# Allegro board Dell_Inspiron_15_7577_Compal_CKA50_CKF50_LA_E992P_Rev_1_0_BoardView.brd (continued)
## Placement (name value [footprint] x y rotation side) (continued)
CH113  10U_0603_6.3V6M  [C_0603]  176.82 115.73 90 top
CH114  10U_0603_6.3V6M  [C_0603]  173.89 91.03 180 top
CH115  10U_0603_6.3V6M  [C_0603]  178.03 115.73 90 top
CH116  10U_0603_6.3V6M  [C_0603]  179.24 115.73 90 top
CH117  10U_0603_6.3V6M  [C_0603]  173.78 95.47 180 top
CH118  10U_0603_6.3V6M  [C_0603]  153.35 85.07 90 top
CH119  10U_0603_6.3V6M  [C_0603]  158.13 84.88 90 top
CH120  10U_0603_6.3V6M  [C_0603]  155.04 81.5 270 top
CH121  10U_0603_6.3V6M  [C_0603]  152.38 83.98 270 top
CH122  10U_0603_6.3V6M  [C_0603]  159.82 84.44 90 top
CH123  10U_0603_6.3V6M  [C_0603]  165.2 81.05 270 top
CH124  10U_0402_6.3V6M  [C_0402]  151.7 85.07 90 top
CH125  10U_0603_6.3V6M  [C_0603]  163.46 83.78 90 top
CH126  10U_0603_6.3V6M  [C_0603]  168.12 80.48 270 top
CH127  10U_0603_6.3V6M  [C_0603]  173.84 85.85 180 top
CH128  10U_0603_6.3V6M  [C_0603]  172.9 80.17 90 top
CH129  22U_0603_6.3V6M  [C_0603]  179.22 65.4 0 top
CH130  22U_0603_6.3V6M  [C_0603]  179.22 64 0 top
CH131  22U_0603_6.3V6M  [C_0603]  179.22 62.61 0 top
CH132  22U_0603_6.3V6M  [C_0603]  179.22 61.21 0 top
CH133  1U_0402_6.3V6K  [C_0402]  172.57 103.28 90 top
CH134  1U_0402_6.3V6K  [C_0402]  180.38 115.92 90 top
CH135  1U_0402_6.3V6K  [C_0402]  172.57 101.5 90 top
CH136  47U_0603_6.3V6M  [C_0603]  173.98 92.25 180 top
CH173  0.1U_0402_10V6K  [C_0402]  285.43 33.43 90 top
CH176  1U_0402_6.3V6K  [C_0402]  281.85 32.53 90 top
CH177  22U_0603_6.3V6M  [C_0603]  301.64 46.83 90 bottom
CH178  22U_0603_6.3V6M  [C_0603]  300.37 46.83 90 bottom
CH179  1U_0402_6.3V6K  [C_0402]  299.31 46.88 90 bottom
CH180  1U_0402_6.3V6K  [C_0402]  273.69 50.97 270 top
CH181  22U_0603_6.3V6M  [C_0603]  275.8 53.5 180 top
CH182  22U_0603_6.3V6M  [C_0603]  276.1 51.21 270 top
CH183  1U_0402_6.3V6K  [C_0402]  283.45 44.29 180 top
CH184  10U_0402_6.3V6M  [C_0402]  283.99 45.17 90 top
CH185  10U_0402_6.3V6M  [C_0402]  283.1 45.17 90 top
CH186  0.1U_0402_10V6K  [C_0402]  288.84 31.99 90 top
CH187  1U_0402_6.3V6K  [C_0402]  288.77 30.84 270 top
CH188  1U_0402_6.3V6K  [C_0402]  290.84 40.12 0 top
CH189  0.1U_0402_10V7K  [C_0402]  293.93 34.95 180 top
CH190  0.1U_0402_10V7K  [C_0402]  277.95 41.85 180 top
CH191  0.1U_0402_10V7K  [C_0402]  280.65 40.92 180 top
CH192  0.1U_0402_10V7K  [C_0402]  273.8 30.51 180 top
CH197  0.1U_0402_10V7K  [C_0402]  133.51 87.55 180 bottom
CH200  0.1U_0402_10V6K  [C_0402]  289.96 32.9 90 top
CH201  22U_0603_6.3V6M  [C_0603]  295.44 36.41 90 top
CH202  22U_0603_6.3V6M  [C_0603]  296.65 36.41 90 top
CH203  0.1U_0402_10V6K  [C_0402]  288.91 35.88 0 top
CH204  1U_0402_6.3V6K  [C_0402]  175.29 99.09 180 top
CH205  0.1U_0402_10V7K  [C_0402]  189.9 64.72 90 top
CH206  0.1U_0402_10V7K  [C_0402]  200.19 57.95 270 top
CH207  0.1U_0402_10V7K  [C_0402]  201.32 65.56 0 top
CH208  100P_0402_50V8J  [C_0402]  284.14 31.16 270 top
CH209  100P_0402_50V8J  [C_0402]  300.04 30 90 bottom
CH210  100P_0402_50V8J  [C_0402]  179.85 80.93 90 top
CH211  100P_0402_50V8J  [C_0402]  137.42 99.98 180 bottom
CH212  100P_0402_50V8J  [C_0402]  295.75 34.51 0 top
CH213  0.5P_0402_50V8C  [C_0402]  290.95 31.66 270 top
CH214  0.5P_0402_50V8C  [C_0402]  283.2 42.45 180 top
CH215  10P_0402_25V8J  [C_0402]  283.61 22.77 270 bottom
CI3  0.1U_0402_10V7K  [C_0402]  11.6 53.42 90 bottom
CI4  0.01U_0402_16V7K  [C_0402]  6.71 45.44 270 bottom
CI5  0.1U_0402_10V7K  [C_0402]  9.69 44.53 90 bottom
CI6  0.1U_0402_10V7K  [C_0402]  10.64 44.53 90 bottom
CI7  0.1U_0402_10V7K  [C_0402]  7.72 44.53 90 bottom
CI8  0.1U_0402_10V7K  [C_0402]  8.68 44.53 90 bottom
CI9  0.1U_0402_10V6K  [C_0402]  356.45 29.05 0 top
CI10  0.1U_0402_10V6K  [C_0402]  356.45 28.16 0 top
CI11  47U_0805_6.3V6M  [C_0805]  360.19 24.73 180 top
CI12  10U_0603_6.3V6M  [C_0603]  363.73 23.15 180 bottom
CI13  0.1U_0402_10V6K  [C_0402]  363.25 24.31 180 bottom
CI16  0.1U_0402_10V6K  [C_0402]  362.18 35 90 top
CI17  47U_0805_6.3V6M  [C_0805]  363.83 35.91 180 bottom
CI18  10U_0603_6.3V6M  [C_0603]  363.83 37.37 180 bottom
CI19  0.1U_0402_10V6K  [C_0402]  363.88 38.45 180 bottom
CI20  0.1U_0402_10V6K  [C_0402]  363.07 35 90 top
CI21  100U_1206_6.3V6K  [C_1206]  18.2 63.72 0 top
CI23  0.1U_0402_10V6K  [C_0402]  12.85 37.68 0 bottom
CI24  1U_0402_6.3V6K  [C_0402]  350.14 33.72 90 bottom
CI25  0.1U_0402_10V6K  [C_0402]  18.5 68.29 0 top
CI26  10U_0603_6.3V6M  [C_0603]  18.45 67.21 0 top
CI27  47U_0805_6.3V6M  [C_0805]  18.37 65.69 0 top
CI28  0.1U_0402_10V7K  [C_0402]  21.74 58.56 90 top
CI29  0.1U_0402_10V7K  [C_0402]  20.79 58.56 90 top
CI30  100U_1206_6.3V6K  [C_1206]  364.97 37.81 0 bottom
CI31  47U_0805_6.3V6M  [C_0805]  360.19 22.95 180 top
CL15  0.1U_0402_10V6K  [C_0402]  30.85 45.58 270 top
CL19  0.1U_0402_10V6K  [C_0402]  22.99 49.33 180 bottom
CL20  0.1U_0402_10V6K  [C_0402]  25.77 49.43 180 bottom
CL21  0.1U_0402_10V6K  [C_0402]  24 41.47 270 top
CL22  0.1U_0402_10V6K  [C_0402]  27.71 49.43 0 bottom
CL24  0.1U_0402_10V6K  [C_0402]  22.78 47.4 180 bottom
CL30  0.1U_0402_10V6K  [C_0402]  29.96 41.56 180 bottom
CL31  0.1U_0402_10V6K  [C_0402]  29.96 40.6 180 bottom
CL32  0.1U_0402_10V6K  [C_0402]  25.6 41.57 270 bottom
CL33  10P_1206_2KV8J  [C_1206]  21.25 79.47 90 top
CL34  0.1U_0402_10V6K  [C_0402]  25.77 50.38 180 bottom
CL35  1U_0402_6.3V6K  [C_0402]  24.65 41.57 270 bottom
CL36  10P_0402_25V8J  [C_0402]  21.88 45.58 90 bottom
CL37  10P_0402_25V8J  [C_0402]  21.88 44.71 270 bottom
CL39  1U_0402_6.3V6K  [C_0402]  24.09 55.72 0 bottom
CL41  1000P_0402_50V7K  [C_0402]  22.01 65.26 270 top
CL42  0.1U_0402_10V7K  [C_0402]  23.7 41.57 270 bottom
CL43  4.7U_0402_6.3V6M  [C_0402]  29.93 45.58 270 top
CL44  4.7U_0402_6.3V6M  [C_0402]  24.09 47.15 0 top
CL47  0.1U_0402_10V6K  [C_0402]  30.85 45.34 180 bottom
CL48  0.1U_0402_10V6K  [C_0402]  30.85 44.45 180 bottom
CL49  0.1U_0402_25V6  [C_0402]  29.95 65.26 270 top
CL52  1000P_0402_50V7K  [C_0402]  23.91 65.27 270 top
CL53  0.1U_0402_25V6  [C_0402]  24.93 65.26 270 top
CL54  1000P_0402_50V7K  [C_0402]  30.9 65.26 270 top
CL55  0.1U_0402_25V6  [C_0402]  22.96 65.26 270 top
CL56  1000P_0402_50V7K  [C_0402]  26.96 65.26 270 top
CL57  0.1U_0402_25V6  [C_0402]  27.91 65.25 270 top
CLP1  -  [EMIST_SUL-12A2M_1P]  367.77 78.77 180 bottom
CLP2  -  [EMIST_SUL-12A2M_1P]  365.74 39.72 180 bottom
CLP3  -  [EMIST_SUL-12A2M_1P]  343.64 60.23 270 bottom
CLP4  -  [EMIST_SUL-12A2M_1P]  348.13 69.43 229 bottom
CLRP1  SHORT PADS  [SHORTPADS]  294.59 22.77 180 bottom
CN1  22U_0603_6.3V6M  [C_0603]  338.94 34.64 90 top
CN2  .1U_0402_16V7K  [C_0402]  340.08 34.62 90 top
CN6  22U_0603_6.3V6M  [C_0603]  342.49 33.49 270 top
CN7  .1U_0402_16V7K  [C_0402]  341.29 33.51 270 top
CN9  10P_0402_25V8J  [C_0402]  341.22 34.94 90 top
CN19  0.1U_0402_16V7K  [C_0402]  264.97 11.13 180 top
CN20  0.1U_0402_10V7K  [C_0402]  344.67 42.51 0 top
CN21  0.1U_0402_10V7K  [C_0402]  344.67 41.56 0 top
CN22  10U_0603_6.3V6M  [C_0603]  270.1 11.65 90 top
CP3  0.01U_0402_16V7K  [C_0402]  328.16 46.57 180 top
CP4  0.1U_0402_10V6K  [C_0402]  328.16 47.53 180 top
CP5  0.1U_0402_10V6K  [C_0402]  341.53 51.91 0 top
CP6  0.1U_0402_10V6K  [C_0402]  341.53 51.02 0 top
CP7  0.01U_0402_16V7K  [C_0402]  341.53 52.8 0 top
CP8  4.7U_0603_6.3V6K  [C_0603]  337.03 40.1 0 top
CP9  0.1U_0402_10V6K  [C_0402]  334.44 40.29 180 top
CP10  0.01U_0402_16V7K  [C_0402]  334.44 39.4 180 top
CP11  0.1U_0402_10V6K  [C_0402]  336.02 40.24 270 top
CP12  0.1U_0402_10V6K  [C_0402]  334.11 49.99 90 top
CP13  0.1U_0402_10V6K  [C_0402]  336.49 49.99 0 top
CP14  0.01U_0402_16V7K  [C_0402]  336.49 50.88 0 top
CP15  0.1U_0402_10V6K  [C_0402]  340.53 39.32 90 top
CP16  0.1U_0402_10V6K  [C_0402]  339.64 39.32 90 top
CP17  0.1U_0402_10V6K  [C_0402]  330.05 39.45 90 top
CP18  0.1U_0402_10V6K  [C_0402]  330.94 39.45 90 top
CP19  0.1U_0402_10V6K  [C_0402]  332.51 37.16 90 top
CP20  0.1U_0402_10V6K  [C_0402]  333.4 37.16 90 top
CP21  0.1U_0402_10V6K  [C_0402]  335.7 37.16 90 top
CP22  0.1U_0402_10V6K  [C_0402]  334.81 37.16 90 top
CP23  0.1U_0402_10V6K  [C_0402]  338.42 49.9 270 top
CP24  0.1U_0402_10V6K  [C_0402]  329.91 51.78 0 top
CP25  0.01U_0402_16V7K  [C_0402]  339.26 41.87 0 top
CP26  0.1U_0402_10V6K  [C_0402]  329.91 50.89 0 top
CP27  1U_0402_6.3V6K  [C_0402]  328.41 42.95 180 top
CP28  22U_0603_6.3V6M  [C_0603]  337.05 38.59 0 top
CP29  22U_0603_6.3V6M  [C_0603]  327.53 48.45 90 top
CP47  0.1U_0402_16V7K  [C_0402]  331.7 49.91 180 top
CR4  6.8P_0402_50V8C  [C_0402]  13.5 23.32 90 bottom
CR5  4.7U_0603_6.3V6K  [C_0603]  20.37 40.3 0 top
CR6  0.1U_0402_10V7K  [C_0402]  20.92 39.21 0 top
CR7  1U_0402_6.3V6K  [C_0402]  15.53 23.32 90 bottom
CR8  1U_0402_6.3V6K  [C_0402]  11.14 29.75 0 bottom
CR9  0.1U_0402_10V7K  [C_0402]  17.31 32.16 180 bottom
CR10  4.7U_0603_6.3V6K  [C_0603]  17.86 33.25 180 bottom
CS12  1000P_0402_50V7K  [C_0402]  243.55 30.4 90 bottom
CS13  0.1U_0402_10V6K  [C_0402]  244.44 30.4 90 bottom
CS14  1U_0402_6.3V6K  [C_0402]  245.33 30.4 90 bottom
CS15  10U_0603_6.3V6M  [C_0603]  246.48 30.51 90 bottom
CS25  0.01U_0402_16V7K  [C_0402]  246.67 24.51 90 top
CS26  0.01U_0402_16V7K  [C_0402]  245.78 24.51 90 top
CS27  0.01U_0402_16V7K  [C_0402]  249.02 24.58 90 top
CS28  0.01U_0402_16V7K  [C_0402]  249.91 24.58 90 top
CT1  0.22U_0201_6.3V  [C_0201]  347.22 51.59 0 bottom
CT2  0.22U_0201_6.3V  [C_0201]  347.22 52.23 0 bottom
CT3  0.22U_0201_6.3V  [C_0201]  347.22 49.05 0 bottom
CT4  0.22U_0201_6.3V  [C_0201]  347.22 53.5 0 bottom
CT5  0.22U_0201_6.3V  [C_0201]  347.22 56.04 0 bottom
CT6  0.1U_0201_6.3V6K  [C_0201]  357.73 46.73 90 bottom
CT7  0.1U_0201_6.3V6K  [C_0201]  357.1 46.73 90 bottom
CT8  0.1U_0201_6.3V6K  [C_0201]  356.46 46.73 90 bottom
CT9  0.1U_0201_6.3V6K  [C_0201]  355.83 46.73 90 bottom
CT10  0.1U_0201_6.3V6K  [C_0201]  354.56 46.73 90 bottom
CT11  0.1U_0201_6.3V6K  [C_0201]  353.29 46.73 90 bottom
CT12  0.22U_0201_6.3V  [C_0201]  347.22 52.86 0 bottom
CT13  0.22U_0201_6.3V  [C_0201]  347.22 50.96 0 bottom
CT14  0.22U_0201_6.3V  [C_0201]  347.22 50.32 0 bottom
CT15  0.22U_0201_6.3V  [C_0201]  347.22 48.42 0 bottom
CT16  0.22U_0201_6.3V  [C_0201]  347.22 49.69 0 bottom
CT18  0.22U_0201_6.3V  [C_0201]  347.22 54.13 0 bottom
CT21  0.22U_0201_6.3V  [C_0201]  347.22 56.67 0 bottom
CT23  0.1U_0201_6.3V6K  [C_0201]  355.19 46.73 90 bottom
CT24  0.1U_0201_6.3V6K  [C_0201]  353.92 46.73 90 bottom
CT25  0.1U_0201_6.3V6K  [C_0201]  352.59 44.06 90 top
CT26  0.1U_0201_6.3V6K  [C_0201]  353.23 44.06 90 top
CT27  0.1U_0201_6.3V6K  [C_0201]  352.02 46.73 90 bottom
CT28  0.1U_0201_6.3V6K  [C_0201]  352.65 46.73 90 bottom
CT29  0.1U_0201_6.3V6K  [C_0201]  350.75 46.73 90 bottom
CT30  0.1U_0201_6.3V6K  [C_0201]  351.38 46.73 90 bottom
CT31  0.1U_0201_6.3V6K  [C_0201]  350.11 46.73 90 bottom
CT32  0.1U_0201_6.3V6K  [C_0201]  349.48 46.73 90 bottom
CT33  0.1U_0201_6.3V6K  [C_0201]  348.21 46.73 90 bottom
CT34  0.1U_0201_6.3V6K  [C_0201]  348.84 46.73 90 bottom
CT35  0.1U_0201_6.3V6K  [C_0201]  351.96 44.06 90 top
CT36  0.1U_0201_6.3V6K  [C_0201]  351.32 44.06 90 top
CT37  27P_0402_50V8J  [C_0402]  347.14 61.37 180 bottom
CT38  27P_0402_50V8J  [C_0402]  348.01 61.37 0 bottom
CT39  0.22U_0201_6.3V  [C_0201]  354.14 62.1 225 bottom
CT40  0.22U_0201_6.3V  [C_0201]  353.61 62.63 225 bottom
CT41  0.22U_0201_6.3V  [C_0201]  352.53 63.24 225 bottom
CT42  0.22U_0201_6.3V  [C_0201]  352.93 62.84 225 bottom
CT43  0.1U_0201_6.3V6K  [C_0201]  351.43 46.54 90 top
CT44  0.1U_0201_6.3V6K  [C_0201]  352 46.54 90 top
CT45  0.1U_0201_6.3V6K  [C_0201]  362.52 45.43 0 bottom
CT46  0.1U_0201_6.3V6K  [C_0201]  357.13 51.97 0 top
CT47  1U_0201_6.3V6M  [C_0201]  357.52 59.15 180 top
CT48  1U_0201_6.3V6M  [C_0201]  361.38 55.4 0 top
CT49  1U_0201_6.3V6M  [C_0201]  356.72 61.79 270 top
CT50  10U_0402_6.3V6M  [C_0402]  361.6 59.78 0 top
CT51  10U_0402_6.3V6M  [C_0402]  361.6 60.67 0 top
CT52  10U_0402_6.3V6M  [C_0402]  361.6 61.56 0 top
CT53  10U_0402_6.3V6M  [C_0402]  361.66 58.89 0 top
CT54  1U_0201_6.3V6M  [C_0201]  354.46 41.11 0 top
CT55  1U_0201_6.3V6M  [C_0201]  350.59 53.13 180 top
CT56  1U_0201_6.3V6M  [C_0201]  348.24 47.34 0 top
CT57  1U_0201_6.3V6M  [C_0201]  354.46 41.81 0 top
CT58  1U_0201_6.3V6M  [C_0201]  354.46 42.54 0 top
CT59  1U_0201_6.3V6M  [C_0201]  353.93 51.89 270 top
CT60  1U_0201_6.3V6M  [C_0201]  354.5 54.62 270 top
CT61  1U_0201_6.3V6M  [C_0201]  356.41 54.43 270 top
CT62  1U_0201_6.3V6M  [C_0201]  357.2 55.09 0 top
CT63  1U_0201_6.3V6M  [C_0201]  354.46 56.56 0 top
CT64  1U_0201_6.3V6M  [C_0201]  356.4 55.06 90 top
CT65  1U_0201_6.3V6M  [C_0201]  355.57 58.36 90 top
CT66  1U_0201_6.3V6M  [C_0201]  355 58.36 90 top
CT67  1U_0201_6.3V6M  [C_0201]  354.43 58.36 90 top
CT68  1U_0201_6.3V6M  [C_0201]  353.86 58.36 90 top
CT69  1U_0201_6.3V6M  [C_0201]  353.29 57.2 180 top
CT70  1U_0201_6.3V6M  [C_0201]  351.76 53.49 270 top
CT71  1U_0201_6.3V6M  [C_0201]  350.59 53.7 180 top
CT72  1U_0201_6.3V6M  [C_0201]  350.59 54.27 180 top
CT73  47U_0603_6.3V6M  [C_0603]  366.14 58.31 90 top
CT74  47U_0603_6.3V6M  [C_0603]  364.87 58.31 90 top
CT75  47U_0603_6.3V6M  [C_0603]  367.41 58.31 90 top
CT77  1U_0201_6.3V6M  [C_0201]  352.69 51.97 180 top
CT78  1U_0201_6.3V6M  [C_0201]  356.53 51.99 270 top
CT79  1U_0201_6.3V6M  [C_0201]  354.5 52.83 90 top
CT80  1U_0201_6.3V6M  [C_0201]  355.71 53.21 90 top
CT81  10U_0402_6.3V6M  [C_0402]  347.65 58.13 180 top
CT82  10U_0402_6.3V6M  [C_0402]  347.65 59.08 180 top
CT83  1U_0201_6.3V6M  [C_0201]  349.64 57.56 180 top
CT84  1U_0201_6.3V6M  [C_0201]  347.42 59.91 180 top
CT85  1U_0201_6.3V6M  [C_0201]  351.8 55.63 270 top
CT86  1U_0201_6.3V6M  [C_0201]  353.28 55.86 90 top
CT88  0.1U_0402_10V6K  [C_0402]  354.8 71.41 270 bottom
CT90  22U_0603_6.3V6M  [C_0603]  365.61 66.26 0 bottom
CT91  22U_0603_6.3V6M  [C_0603]  365.67 67.53 0 bottom
CT92  22U_0603_6.3V6M  [C_0603]  365.61 65.05 0 bottom
CT93  22U_0603_6.3V6M  [C_0603]  366.69 70.12 315 top
CT94  0.01U_0402_50V7K  [C_0402]  368.96 71.97 0 top
CT95  0.01U_0402_50V7K  [C_0402]  368.96 71.08 0 top
CT96  0.01U_0402_50V7K  [C_0402]  369.88 70.2 180 top
CT97  0.01U_0402_50V7K  [C_0402]  369.88 68.1 180 top
CT98  2.2U_0603_16V6K  [C_0603]  356.91 67.59 180 bottom
CT99  4.7U_0603_10V6K  [C_0603]  357.35 66 180 bottom
CT100  4.7U_0603_10V6K  [C_0603]  357.88 71.13 315 top
CT101  1U_0402_6.3V6K  [C_0402]  353.86 71.41 270 bottom
CT102  1U_0201_6.3V6M  [C_0201]  355.68 72.99 180 bottom
CT103  10U_0402_6.3V6M  [C_0402]  354.45 67.72 180 bottom
CT104  0.22U_0402_10V4Z  [C_0402]  364.4 76.28 90 bottom
CT106  1U_0603_25V6K  [C_0603]  372.21 73.31 90 bottom
CT108  0.22U_0201_6.3V  [C_0201]  347.22 55.4 0 bottom
CT109  0.22U_0201_6.3V  [C_0201]  347.22 54.77 0 bottom
CT110  0.22U_0201_6.3V  [C_0201]  347.22 57.31 0 bottom
CT111  0.22U_0201_6.3V  [C_0201]  347.22 57.94 0 bottom
CT112  220P_0201_25V7K  [C_0201]  364.47 74.67 90 bottom
CT113  220P_0201_25V7K  [C_0201]  365.91 73.73 0 bottom
CT114  2200P_0402_25V7K  [C_0402]  91.86 68.09 90 bottom
CT115  47U_0603_6.3V6M  [C_0603]  360.59 56.29 0 top
CT116  47U_0603_6.3V6M  [C_0603]  360.59 57.5 0 top
CT117  0.1U_0201_6.3V6K  [C_0201]  364.69 97.74 0 bottom
CTH1  0.1U_0201_10V6K  [C_0201]  93.55 65.5 180 bottom
CTH2  0.01U_0402_16V7K  [C_0402]  160.5 89.28 0 top
CTH3  2200P_0402_25V7K  [C_0402]  90.78 66.25 90 bottom
CTH4  2200P_0402_25V7K  [C_0402]  91.86 66.25 90 bottom
CTH5  2200P_0402_25V7K  [C_0402]  90.78 68.09 90 bottom
CTPM1  0.1U_0402_16V7K  [C_0402]  292.65 9.69 270 bottom
CTPM2  10U_0402_6.3V6M  [C_0402]  294.82 11.93 0 bottom
CTPM3  10U_0402_6.3V6M  [C_0402]  286.37 12.09 180 bottom
CTPM4  0.1U_0201_10V6K  [C_0201]  286.14 12.86 180 bottom
CTPM5  10U_0402_6.3V6M  [C_0402]  285.28 14.52 270 bottom
CTPM6  0.1U_0402_16V7K  [C_0402]  292.52 18.81 90 bottom
CTPM7  0.1U_0402_16V7K  [C_0402]  286.68 15.45 90 bottom
CV576  8.2P_0402_50V8D  [C_0402]  91.61 51.96 90 top
CV577  10U_0603_6.3V6M  [C_0603]  92.69 52.03 90 top
CV578  1U_0603_25V6K  [C_0603]  84.24 37.3 180 bottom
CV579  0.1U_0402_25V6  [C_0402]  88.75 40.97 90 bottom
CV580  0.1U_0402_10V6K  [C_0402]  87.91 55.27 0 bottom
CV581  0.1U_0402_10V6K  [C_0402]  87.91 56.23 0 bottom
CV582  0.1U_0402_10V6K  [C_0402]  287.2 64.86 180 top
CV583  8.2P_0402_50V8D  [C_0402]  287.2 63.91 180 top
CV584  10U_0603_6.3V6M  [C_0603]  287.69 66 180 top
CV585  0.1U_0402_10V6K  [C_0402]  87.91 57.43 0 bottom
CV586  0.1U_0402_10V6K  [C_0402]  87.91 58.38 0 bottom
CV587  0.1U_0402_10V6K  [C_0402]  87.91 59.53 0 bottom
CV588  0.1U_0402_10V6K  [C_0402]  87.91 60.48 0 bottom
CV589  0.1U_0402_10V6K  [C_0402]  87.91 61.56 0 bottom
CV590  0.1U_0402_10V6K  [C_0402]  87.91 62.51 0 bottom
CV591  0.1U_0402_10V6K  [C_0402]  87.91 54 0 bottom
CV592  0.1U_0402_10V6K  [C_0402]  87.91 53.05 0 bottom
CV597  10U_0603_6.3V6M  [C_0603]  366.23 90.75 180 bottom
CV598  0.1U_0402_10V6K  [C_0402]  365.7 91.85 180 bottom
CV599  0.1U_0402_25V6  [C_0402]  365.85 82.9 0 bottom
CV600  0.1U_0402_25V6  [C_0402]  367.2 90.58 90 bottom
CV601  0.1U_0402_25V6  [C_0402]  366.66 97.34 0 bottom
CV922  10P_0402_25V8J  [C_0402]  89.76 40.97 90 bottom
CVGA1  10U_0603_6.3V6M  [C_0603]  316.59 34.25 90 top
CVGA2  10U_0603_6.3V6M  [C_0603]  321.67 43.34 180 top
CVGA3  0.1U_0402_16V4Z  [C_0402]  320.26 42.26 0 top
CVGA4  0.1U_0402_16V4Z  [C_0402]  316.27 31.07 90 top
CVGA5  2.2U_0402_6.3V6M  [C_0402]  316.56 39.68 180 top
CVGA6  0.1U_0402_16V4Z  [C_0402]  315.65 40.63 0 top
CVGA7  0.1U_0402_16V4Z  [C_0402]  324.35 36.22 0 top
CVGA8  0.1U_0402_16V4Z  [C_0402]  312.84 34.24 90 top
CVGA9  0.1U_0402_16V4Z  [C_0402]  317.16 31.07 90 top
CVGA10  0.1U_0402_16V4Z  [C_0402]  320.14 33.8 90 top
CVGA11  0.1U_0402_16V4Z  [C_0402]  321.1 33.8 90 top
CVGA12  0.1U_0402_16V4Z  [C_0402]  321.98 31.58 90 top
CVGA13  0.1U_0402_16V4Z  [C_0402]  322.94 31.58 90 top
CVGA14  4.7U_0603_6.3V6K  [C_0603]  323.57 42.13 90 top
CVGA15  0.1U_0402_16V4Z  [C_0402]  324.64 42.18 90 top
CVGA16  2.2P_0402_50V8C  [C_0402]  370.24 123.62 90 top
CVGA17  2.2P_0402_50V8C  [C_0402]  370.24 120.48 90 top
CVGA18  2.2P_0402_50V8C  [C_0402]  370.24 116.26 90 top
CVGA19  2.2P_0402_50V8C  [C_0402]  372.96 123.62 270 top
CVGA20  2.2P_0402_50V8C  [C_0402]  372.96 120.48 270 top
CVGA21  2.2P_0402_50V8C  [C_0402]  372.96 116.26 270 top
CVGA22  0.01U_0402_16V7K  [C_0402]  370.42 119.73 0 bottom
CVGA23  10P_0402_50V  [C_0402]  371.44 119.08 270 top
CVGA24  10P_0402_50V  [C_0402]  371.62 114.76 270 top
CZ4  470P_0402_50V7K  [C_0402]  260.77 35.83 90 top
CZ6  0.01U_0402_16V7K  [C_0402]  261.72 35.83 90 top
CZ8  10U_0603_6.3V6M  [C_0603]  259.63 35.78 90 top
CZ9  10U_0603_6.3V6M  [C_0603]  262.87 35.88 90 top
CZ11  1U_0603_10V6K  [C_0603]  260.07 30.25 270 top
CZ12  1U_0603_10V6K  [C_0603]  263.44 31.27 0 top
CZ28  0.1U_0402_10V6K  [C_0402]  181.27 110.45 90 bottom
CZ41  0.1U_0402_10V6K  [C_0402]  90.65 51.96 90 top
CZ44  1U_0402_6.3V6K  [C_0402]  287.2 63.02 180 top
CZ47  0.1U_0402_10V6K  [C_0402]  182.16 102 90 top
CZ49  0.1U_0402_10V6K  [C_0402]  222.48 54.4 180 top
CZ57  2200P_0402_25V7K  [C_0402]  227.12 53.6 0 top
CZ86  0.1U_0402_10V7K  [C_0402]  183.54 105.1 270 bottom
CZ88  1U_0402_6.3V6K  [C_0402]  184.32 111.46 90 bottom
CZ96  1U_0402_6.3V6K  [C_0402]  183.36 111.47 90 bottom
CZ97  0.1U_0402_25V6  [C_0402]  185.4 111.9 90 bottom
CZ102  0.1U_0402_10V6K  [C_0402]  241.52 22.95 0 top
CZ108  0.22U_0402_10V4Z  [C_0402]  276.31 64.86 0 top
D1  -  [BAT54C-7-F_SOT23-3]  341.12 10.14 90 top
D5223  -  [L03ESDL5V0CC3-2_SOT23-3]  224.69 27.12 270 bottom
D5225  -  [TVNST52302AB0_SOT523-3]  219.28 30.9 90 bottom
D5226  -  [TVNST52302AB0_SOT523-3]  214.45 30.93 270 bottom
DA1  -  [AZC199-02SPR7G_SOT23-3]  288.1 60.2 45 bottom
DA2  AZ5125-02S.R7G_SOT23-3  [AZ5125-02SPR7G_SOT23-3]  327.36 17.91 90 top
DA3  AZ5125-02S.R7G_SOT23-3  [AZ5125-02SPR7G_SOT23-3]  327.36 22.35 90 top
DA4  AZ5123-02S.R7G_SOT23-3  [AZ5123-02SPR7G_SOT23-3]  365.82 17.81 0 bottom
DA5  -  [L03ESDL5V0CC3-2_SOT23-3]  354.81 5.4 0 top
DA6  -  [TVNST52302AB0_SOT523-3]  362.88 17.68 0 top
DC2  BAT54CW_SOT323-3  [BAT54CW-7-F_SOT323-3]  265.09 17.37 0 bottom
DE4  AZC099-04S.R7G_SOT23-6  [AZC099-04SPR7G_SOT23-6]  157.39 25.13 180 bottom
DE7  RB751S40T1G_SOD523-2  [AZ5125-01HPR7G_SOD523-2]  100.05 61.31 0 top
DE9  RB751S40T1G_SOD523-2  [AZ5125-01HPR7G_SOD523-2]  310.96 51.62 180 top
DG2  RB751S40T1G_SOD523-2  [AZ5125-01HPR7G_SOD523-2]  205.6 74.97 90 bottom
DG3  RB751S40T1G_SOD523-2  [AZ5125-01HPR7G_SOD523-2]  225.77 62.04 180 top
DG4  RB751S40T1G_SOD523-2  [AZ5125-01HPR7G_SOD523-2]  224.08 63.97 90 top
DG7  RB751S40T1G_SOD523-2  [AZ5125-01HPR7G_SOD523-2]  225.63 60.53 180 top
DG8  RB751S40T1G_SOD523-2  [AZ5125-01HPR7G_SOD523-2]  304.96 43.32 0 top
DG9  -  [BAT54A-7-F_SOT23-3]  194.98 73.46 0 bottom
DG10  RB751S40T1G_SOD523-2  [AZ5125-01HPR7G_SOD523-2]  116.42 85.19 180 bottom
DH1  RB751S40T1G_SOD523-2  [AZ5125-01HPR7G_SOD523-2]  283.38 26.44 90 top
DI1  RB751S40T1G_SOD523-2  [AZ5125-01HPR7G_SOD523-2]  87.48 47.78 0 bottom
DI3  -  [PESD5V0U2BT_SOT23-3]  85.93 45.11 90 bottom
DI7  -  [TVWDF1004AD0_DFN9]  359.2 30.3 270 top
DI8  -  [AZC199-02SPR7G_SOT23-3]  358.56 32.54 90 bottom
DI9  -  [TVWDF1004AD0_DFN9]  360.86 38.71 0 top
DI10  -  [AZC199-02SPR7G_SOT23-3]  359.74 42.64 90 bottom
DI11  -  [AZC199-02SPR7G_SOT23-3]  19.85 59.63 180 bottom
DI12  -  [TVWDF1004AD0_DFN9]  18.21 61.99 270 top
DN1  RB751S40T1G_SOD523-2  [AZ5125-01HPR7G_SOD523-2]  345.14 45.29 180 top
DN2  RB751S40T1G_SOD523-2  [AZ5125-01HPR7G_SOD523-2]  343.07 44.05 180 top
DT1  RB751S40T1G_SOD523-2  [AZ5125-01HPR7G_SOD523-2]  366.18 71.48 90 bottom
DT2  PESD5V0H1BSF_SOD962-2-2  [ESD8011MUT5G_X3DFN2-2]  372.78 68.79 90 bottom
DT3  PESD5V0H1BSF_SOD962-2-2  [ESD8011MUT5G_X3DFN2-2]  372.78 67.74 270 bottom
DT4  PESD5V0H1BSF_SOD962-2-2  [ESD8011MUT5G_X3DFN2-2]  372.34 74.55 90 top
DT5  PESD5V0H1BSF_SOD962-2-2  [ESD8011MUT5G_X3DFN2-2]  372.34 73.51 270 top
DT6  PESD5V0H1BSF_SOD962-2-2  [ESD8011MUT5G_X3DFN2-2]  372.4 65.89 270 top
DT7  PESD5V0H1BSF_SOD962-2-2  [ESD8011MUT5G_X3DFN2-2]  372.4 66.93 90 top
DT8  PESD5V0H1BSF_SOD962-2-2  [ESD8011MUT5G_X3DFN2-2]  373.29 65.06 270 bottom
DT9  PESD5V0H1BSF_SOD962-2-2  [ESD8011MUT5G_X3DFN2-2]  373.29 66.11 90 bottom
DT10  -  [TVWDF1004AD0_DFN9]  372.4 72.15 270 bottom
DT11  -  [TVNST52302AB0_SOT523-3]  366.75 75.02 90 bottom
DT13  PESD5V0H1BSF_SOD962-2-2  [ESD8011MUT5G_X3DFN2-2]  373.17 75.7 90 bottom
DT14  PESD5V0H1BSF_SOD962-2-2  [ESD8011MUT5G_X3DFN2-2]  372.4 71.3 270 top
DT15  -  [PESD24VS2UT_SOT23-3]  369.16 75.94 0 bottom
DV1  RB751S40T1G_SOD523-2  [AZ5125-01HPR7G_SOD523-2]  292.57 22.58 180 top
DV2  BAT54CW_SOT323-3~D  [BAT54CW-7-F_SOT323-3]  89.32 47.84 90 top
DV3  BAT54CW_SOT323-3~D  [BAT54CW-7-F_SOT323-3]  91.67 55.84 90 top
DV12  -  [PESD5V0U2BT_SOT23-3]  289.73 59.69 0 top
DVGA1  -  [LRB551V-30T1G_SOD323-2]  368.91 116.52 270 bottom
DZ1  RB751S40T1G_SOD523-2  [AZ5125-01HPR7G_SOD523-2]  242.74 24.41 180 top
DZ2  RB751S40T1G_SOD523-2  [AZ5125-01HPR7G_SOD523-2]  277.47 66.89 180 top
EC5205  6.8P_0402_50V8C  [C_0402]  286.81 62.03 45 bottom
EC5206  6.8P_0402_50V8C  [C_0402]  286.17 61.39 225 bottom
F1  0.5A_13.2V_NANOSMDC050F-13.2-2  [F_NANOSMDC050F-13P2-2]  196.84 30.72 0 bottom
F2  SMD1812P150TF/24 1.5A UL/CSA/TUV  [F_SMD1812P110TF-24]  87.66 35.08 0 bottom
FD1  FIDUCAL  [FIDUCIAL_C40M80]  364.35 122.57 180 bottom
FD2  FIDUCIAL  [FIDUCIAL_C40M80]  34.56 23.85 0 top
FD3  FIDUCAL  [FIDUCIAL_C40M80]  30.54 24.46 180 bottom
FD4  FIDUCIAL  [FIDUCIAL_C40M80]  373.24 129.17 0 top
FVGA1  1.1A_6V_SPR-P110  [F_SPR-P110]  371.09 118.27 180 bottom
H1  -  [H_2P8-G]  7.4 103.3 0 top
H2  -  [H_2P8-G]  7.4 78.4 0 top
H3  -  [H_2P8-G]  7.4 24 0 top
H4  -  [H_2P8-G]  24.5 29 0 top
H5  -  [H_3P3]  73.42 59 0 top
H7  -  [H_2P8-G]  117.2 137.3 0 top
H8  -  [H_2P8-G]  126 21.5 0 top
H9  -  [H_2P8N]  192.27 143.5 0 top
H10  -  [H_2P8-G]  235 21.5 0 top
H11  -  [H_2P8-G]  262.3 137.3 0 top
H13  -  [H_3P3]  311.32 42.55 0 top
H14  -  [H_2P8X3P4-G]  360.7 116.7 270 top
H15  -  [H_2P8-G]  357.5 79.9 0 top
H16  -  [H_2P8-G]  376 139 0 top
H17  -  [H_2P8-G]  362.25 9 0 top
H18  -  [H_3P0-G]  377.5 79.47 0 top
H19  -  [H_3P0-G]  377.5 61.23 0 top
H20  -  [H_2P8X3P4N]  372.4 38.65 90 top
H21  -  [H_2P8N]  59.35 60.15 90 top
H22  -  [H_2P8X3P4N]  360.39 3.5 90 top
H23  -  [H_4P5N]  357.35 16.52 0 top
HCPU1  -  [H_4P0-G]  132.81 116.09 0 top
HCPU2  -  [H_4P0-G]  129.32 72.62 0 top
HCPU3  -  [H_3P7-G]  188.75 72.7 0 top
HCPU4  -  [H_3P7-G]  190.5 110.5 0 top
HDA1  ALC3246-CG-GP  [ALC3246-CG_MQFN48_6X6-S]  341.4 22.26 0 top
HGPU1  -  [H_4P0-G]  253.76 130 0 top
HGPU2  -  [H_4P0-G]  271.45 72.51 0 top
HT1  100K_0402_1%_TSM0B104F4251RZ  [R_0402]  160.5 90.17 0 top
JBL1  ACES_51575-00401-001  [ACES_51575-00401-001_4P-T]  193.75 28.93 180 bottom
JCAM1  ACES_50228-0067N-001  [ACES_50228-0067N-001_6P]  296.14 60.99 315 bottom
JCRT1  C-K_80454-5K1-152  [C-K_80454-5K1-152_15P]  376.2 126.33 270 bottom
JDEG1  JXT_FP241AH-010GAAM  [JXT_FP241AH-010GAAM_10P]  325.25 6.93 180 bottom
JDIMM1  DEREN_40-42271-26001RHF  [DEREN_40-42271-26001RHF_260P-T]  102.83 42.9 0 bottom
JDIMM2  DEREN_40-42271-26001RHF  [DEREN_40-42271-26001RHF_260P-T]  179.33 42.9 0 bottom
JEDP1  ACES_59003-04006-001  [ACES_59003-04006-001_40P]  95.33 41.25 270 bottom
JESPI1  JXT_FP241AH-010GAAM  [JXT_FP241AH-010GAAM_10P]  299.76 7.08 180 bottom
JFAN1  ACES_50278-0040N-001  [ACES_50278-0040N-001_4P]  97.25 64.95 270 top
JFAN2  ACES_50278-0040N-001  [ACES_50278-0040N-001_4P]  313.45 48.05 90 top
JHDD1  ACES_51625-01201-001  [ACES_51625-01201-001_12P]  248.6 28.15 180 bottom
JHDMI1  CONCR_099A3AC19JBLCNF  [CONCR_099A3AC19JBLCNF_19P]  371.8 97.1 270 bottom
JHP1  SINGA_2SJ3095-106111F  [SINGA_2SJ3095-106111F_6P]  370.6 14.95 90 bottom
JKB1  ACES_50699-03001-P01  [ACES_50699-03001-P01_30P]  108.58 31.4 180 bottom
JLAN  SANTA_130460-N  [SANTA_130460-N_8P]  12.85 93.57 90 bottom
JLED  ACES_51575-00401-001  [ACES_51575-00401-001_4P-T]  204.65 28.95 180 bottom
JNGFF1  CONCR_213EAAA32FA  [CONCR_213EAAA32FA_67P]  344.85 33.3 90 bottom
JNGFF2  BELLW_SD-80159-4221  [BELLW_SD-80159-4221_67P-T]  273.82 25.78 270 bottom
JPW  ACES_51530-01001-P01  [ACES_51530-01001-P01_10P-T]  217.65 28.58 180 bottom
JPZ1  PAD-OPEN1X3M  [JUMP_43X118]  256.6 34 180 top
JPZ2  PAD-OPEN1X3M  [JUMP_43X118]  265.9 34.89 0 top
JREAD1  T-SOL_156-1001902607  [T-SOL_156-1001902607_11P]  17.1 35.32 270 top
JRTC  ACES_50273-0020N-001  [ACES_50273-0020N-001_2P-T]  261.5 19.86 0 bottom
JSPK1  ACES_50278-0040N-001  [ACES_50278-0040N-001_4P]  323.15 14.25 0 top
JTP  ACES_51524-0080N-001  [ACES_51524-0080N-001_8P]  149.45 29.45 180 bottom
JUSB1  ACON_TCRA2-9R1394  [ACON_TCRA2-9R1394_9P]  366.88 45.7 270 bottom
JUSB2  ACON_TCRA2-9R1394  [ACON_TCRA2-9R1394_9P]  366.88 24.6 270 bottom
JUSB3  ACON_TCRA2-9R1394  [ACON_TCRA2-9R1394_9P]  15.12 71.15 90 bottom
JUSBC1  JAE_DX07S024JJ7R1200  [JAE_DX07S024JJ7R1200_24P-T]  375.85 67.73 90 top
JXDP1  SAMTE_BSH-030-01-L-D-A-TR  [SAMTE_BSH-030-01-L-D-A-TR_60P]  210.87 62.06 180 bottom
LA1  BLM15PX471SN1D_2P  [MURAT_BLM15PX471SN1D_2P]  337.22 21.47 0 top
LA19  BLM15PX330SN1D 0402  [MURAT_BLM15BD601SN1D_2P]  366.73 12.99 0 bottom
LA20  BLM15AX700SN1D_2P  [MURAT_BLM15AX700SN1D_2P]  353.51 12.89 0 top
LA21  BLM15AX700SN1D_2P  [MURAT_BLM15AX700SN1D_2P]  351.74 9.3 0 top
LA22  BLM15PX330SN1D 0402  [MURAT_BLM15BD601SN1D_2P]  362.43 14.89 90 bottom
LA23  BLM15PX181SN1D_2P  [MURAT_BLM15PX181SN1D_2P]  329.35 21.79 270 top
LA24  BLM15PX181SN1D_2P  [MURAT_BLM15PX181SN1D_2P]  329.35 22.69 90 top
LA25  BLM15PX181SN1D_2P  [MURAT_BLM15PX181SN1D_2P]  329.35 17.15 270 top
LA26  BLM15PX181SN1D_2P  [MURAT_BLM15PX181SN1D_2P]  329.35 18.18 90 top
LED3  HT-F196BP5_WHITE  [LED_HT-F196BP5_2P]  284.25 7.52 180 top
LG4  PBY160808T-301Y-N  [CHILI_PBY160808T-300Y-N_2P]  211.25 75 90 bottom
LG5  PBY160808T-300Y-N_2P  [CHILI_PBY160808T-300Y-N_2P]  199.17 84.16 0 top
LG6  PBY160808T-300Y-N_2P  [CHILI_PBY160808T-300Y-N_2P]  213.85 80.02 90 top
LG7  PBY160808T-300Y-N_2P  [CHILI_PBY160808T-300Y-N_2P]  212.77 76.3 270 bottom
LG8  PBY160808T-300Y-N_2P  [CHILI_PBY160808T-300Y-N_2P]  200.18 91.15 0 top
LG9  PBY160808T-301Y-N  [CHILI_PBY160808T-300Y-N_2P]  208.52 98.91 270 top
LH1  BLM15PX221SN1D_2P  [MURAT_BLM15PX221SN1D_2P]  290.06 30.78 90 top
LH2  BLM15PX221SN1D_2P  [MURAT_BLM15PX221SN1D_2P]  289.79 36.79 180 top
LI1  MCM1012B900F06BP_4P  [INPAQ_MCM1012B900F06BP_4P]  82.98 41.43 0 bottom
LI2  MCM1012B900F06BP_4P  [INPAQ_MCM1012B900F06BP_4P]  357.48 39.03 90 bottom
LI5  MCM1012B900F06BP_4P  [INPAQ_MCM1012B900F06BP_4P]  354.19 31.62 0 bottom
LI8  MCM1012B900F06BP_4P  [INPAQ_MCM1012B900F06BP_4P]  18.07 57.32 90 bottom
LT1  0.6UH_MND-04ABIR60M-XGL_20%  [MAG_MND-04ABIR60M-XGL_2P]  366.24 61.52 270 bottom
LT2  MCM1012B900F06BP_4P  [INPAQ_MCM1012B900F06BP_4P]  368.86 71.66 0 bottom
LT3  MCM1012B900F06BP_4P  [INPAQ_MCM1012B900F06BP_4P]  368.86 70.14 0 bottom
LT4  LQM18PN1R0MFHD_2P  [CHILI_PBY160808T-300Y-N_2P]  360.4 58.64 90 top
LV22  MCM1012B900F06BP_4P  [INPAQ_MCM1012B900F06BP_4P]  291.19 56.97 90 top
LVGA1  BLM15BB220SN1D  [MURAT_BLM15BD601SN1D_2P]  371.19 123.62 0 top
LVGA2  BLM15BB220SN1D  [MURAT_BLM15BD601SN1D_2P]  371.19 120.48 0 top
LVGA3  BLM15BB220SN1D  [MURAT_BLM15BD601SN1D_2P]  371.19 116.26 0 top
NOREF  -  []  121.25 13.45 0 top
NOREF#2  -  []  269.67 186.7 0 top
NOREF#3  -  []  311.32 42.55 0 top
NOREF#4  -  []  117.2 137.3 0 top
NOREF#5  -  []  377.5 61.23 0 top
NOREF#6  -  []  172.89 58.77 0 top
NOREF#7  -  []  190.5 110.5 0 top
NOREF#8  -  []  7.4 24 0 top
NOREF#9  -  []  24.5 29 0 top
NOREF#10  -  []  129.45 60.86 0 top
NOREF#11  -  []  132.81 116.09 0 top
NOREF#12  -  []  362.25 9 0 top
NOREF#13  -  []  32.35 24.89 0 top
NOREF#14  -  []  190.95 -37.47 0 top
NOREF#15  -  []  271.45 72.51 0 top
NOREF#16  -  []  212.56 27.68 0 top
NOREF#17  -  []  377.5 79.47 0 top
NOREF#18  -  []  129.32 72.62 0 top
NOREF#19  -  []  360.7 116.7 0 top
NOREF#20  -  []  376 139 0 top
NOREF#21  -  []  7.4 78.4 0 top
NOREF#22  -  []  357.5 79.9 0 top
NOREF#23  -  []  262.3 137.3 0 top
NOREF#24  -  []  7.4 103.3 0 top
NOREF#25  -  []  73.42 59 0 top
NOREF#26  -  []  143.1 59.34 90 top
NOREF#27  -  []  253.76 130 0 top
NOREF#28  -  []  188.75 72.7 0 top
NOREF#29  -  []  227.67 123.5 180 bottom
NOREF#30  -  []  158.85 -16.22 180 bottom
NOREF#31  -  []  134.39 54.23 180 bottom
NOREF#32  -  []  210.8 -58.78 180 bottom
PBATT1  ACES_50458-01001-P01  [ACES_50458-01001-P01_10P-T]  53.6 33.5 180 bottom
PC1  1000P_0402_50V7K  [C_0402]  48.88 62.77 90 top
PC2  100P_0402_50V8J  [C_0402]  49.84 62.77 90 top
PC3  1000P_0402_50V7K  [C_0402]  53.87 57.57 0 top
PC4  100P_0402_50V8J  [C_0402]  53.87 56.62 0 top
PC5  0.022U_0402_25V7K  [C_0402]  56.67 36.64 270 bottom
PC6  0.01UF_0402_25V7K  [C_0402]  57.57 36.64 270 bottom
PC7  1000P_0402_50V7K  [C_0402]  57.24 31.91 0 top
PC8  100P_0402_50V8J  [C_0402]  57.24 32.86 0 top
PC10V0  10U_0603_6.3V6M  [C_0603]  114.38 94.71 0 bottom
PC10V1  1U_0603_6.3V6M  [C_0603]  114.4 95.91 0 bottom
PC10V2  22U_0603_6.3V6M  [C_0603]  124.37 90.13 90 bottom
PC10V3  22U_0603_6.3V6M  [C_0603]  125.62 90.12 90 bottom
PC10V4  22U_0603_6.3V6M  [C_0603]  126.85 90.13 90 bottom
PC10V5  680P_0402_50V7K  [C_0402]  123.43 96.68 180 bottom
PC10V6  22P_0603_50V8  [C_0603]  115.99 91.15 90 bottom
PC10V7  0.1U_0402_16V7K  [C_0402]  122.01 91.79 0 bottom
PC12  0.1U_0402_25V6  [C_0402]  64.45 29.53 270 top
PC13  0.1U_0402_25V6  [C_0402]  52.6 30.23 0 top
PC14  0.022U_0402_25V7K  [C_0402]  36.36 49.74 90 top
PC15  0.1U_0402_25V6  [C_0402]  57.84 26.13 180 top
PC16  0.1U_0402_25V6  [C_0402]  60.08 25.86 0 top
PC17  1000P_0402_50V7K  [C_0402]  48.88 62.77 90 bottom
PC18  100P_0402_50V8J  [C_0402]  49.84 62.77 90 bottom
PC18V00  10U_0805_25V6K~D  [C_0805]  278.01 74.99 135 top
PC18V01  0.1U_0603_25V7K  [C_0603]  272.26 82.2 180 top
PC18V02  10U_0805_25V6K~D  [C_0805]  277.75 75.78 180 bottom
PC18V03  330P_0402_50V7K  [C_0402]  266.52 80.38 0 bottom
PC18V04  22U_0603_6.3V6M  [C_0603]  267.44 86.26 180 top
PC18V05  22U_0603_6.3V6M  [C_0603]  267.44 82.45 180 top
PC18V06  22U_0603_6.3V6M  [C_0603]  267.44 84.99 180 top
PC18V07  22U_0603_6.3V6M  [C_0603]  267.44 83.72 180 top
PC18V08  2.2U_0402_16V6K  [C_0402]  269.71 80.55 0 top
PC18V09  0.1U_0402_16V7K  [C_0402]  267.58 77.63 180 bottom
PC18V10  680P_0402_50V7K  [C_0402]  272.34 84.48 180 top
PC18V11  1U_0603_6.3V6M  [C_0603]  267.76 79.47 270 top
PC19  1000P_0402_50V7K  [C_0402]  53.87 56.62 0 bottom
PC20  100P_0402_50V8J  [C_0402]  53.87 57.57 0 bottom
PC25V00  0.1U_0402_16V7K  [C_0402]  175.05 31.37 90 bottom
PC25V01  22U_0603_6.3V6M  [C_0603]  174.66 30.06 0 bottom
PC25V02  22U_0603_6.3V6M  [C_0603]  174.66 28.79 0 bottom
PC25V03  22P_0603_50V8  [C_0603]  163.74 29.43 90 bottom
PC25V04  22U_0603_6.3V6M  [C_0603]  164.42 26.99 90 bottom
PC25V05  22U_0603_6.3V6M  [C_0603]  165.62 26.99 90 bottom
PC25V06  1U_0603_6.3V6M  [C_0603]  173.22 25.14 180 bottom
PC100  1000P_0402_50V7K  [C_0402]  256.39 49.23 90 top
PC101  0.1U_0402_25V6  [C_0402]  248.14 45.18 180 top
PC102  2200P_0402_50V7K  [C_0402]  248.14 46.07 180 top
PC103  10U_0805_25V6K~D  [C_0805]  249.02 47.12 90 top
PC104  10U_0805_25V6K~D  [C_0805]  250.74 47.12 90 top
PC105  1U_0402_25V6K  [C_0402]  255.44 49.23 90 top
PC106  0.1U_0603_25V7K  [C_0603]  252.01 45.3 0 top
PC107  0.1U_0402_25V6  [C_0402]  251.12 37.25 270 top
PC108  1U_0402_6.3V6K  [C_0402]  254.22 37.49 0 top
PC109  22U_0603_6.3V6M  [C_0603]  260.2 39.65 180 bottom
PC110  22U_0603_6.3V6M  [C_0603]  260.2 38.45 180 bottom
PC111  680P_0603_50V7K  [C_0603]  258.67 40.27 90 top
PC112  22U_0603_6.3V6M  [C_0603]  261.34 41.27 180 top
PC113  22U_0603_6.3V6M  [C_0603]  261.33 40.07 180 top
PC114  330P_0402_50V7K  [C_0402]  252.96 36.34 90 top
PC115  2.2U_0402_6.3V6M  [C_0402]  254.08 39.33 0 top
PC200  0.1U_0402_25V6  [C_0402]  104.65 67.85 0 top
PC201  2200P_0402_50V7K  [C_0402]  102.48 72.16 180 top
PC202  10U_0805_25V6K~D  [C_0805]  104.78 70.98 0 top
PC203  10U_0805_25V6K~D  [C_0805]  104.81 69.2 0 top
PC204  1U_0402_25V6K  [C_0402]  101.32 69.55 90 top
PC205  1000P_0402_50V7K  [C_0402]  100.37 69.55 90 top
PC206  0.1U_0603_25V7K  [C_0603]  107.94 70.33 0 top
PC207  10U_0805_6.3V6K  [C_0805]  108.12 66.28 270 top
PC208  10U_0805_6.3V6K  [C_0805]  106.4 66.28 270 top
PC209  1U_0603_10V6K  [C_0603]  114.23 71.65 270 top
PC212  0.033U_0402_16V7K  [C_0402]  111.78 64.17 270 top
PC213  680P_0402_50V7K  [C_0402]  109.39 77.93 90 bottom
PC214  1U_0603_10V6K  [C_0603]  113.14 70.55 90 bottom
PC215  0.1U_0402_10V7K  [C_0402]  114.77 67.78 0 top
PC216  0.1U_0402_10V7K  [C_0402]  114.78 63.99 0 top
PC217  22U_0603_6.3V6M  [C_0603]  123.27 80.44 90 bottom
PC218  22U_0603_6.3V6M  [C_0603]  124.5 80.42 90 bottom
PC219  22U_0603_6.3V6M  [C_0603]  116.82 83.53 0 bottom
PC220  22U_0603_6.3V6M  [C_0603]  125.71 80.42 90 bottom
PC221  22U_0603_6.3V6M  [C_0603]  118.2 80.44 90 bottom
PC222  22U_0603_6.3V6M  [C_0603]  119.48 80.42 90 bottom
PC223  22U_0603_6.3V6M  [C_0603]  120.75 80.42 90 bottom
PC224  22U_0603_6.3V6M  [C_0603]  122.02 80.42 90 bottom
PC300  4.7U_0603_6.3V6K  [C_0603]  84.36 42.84 0 top
PC301  10U_0805_25V6K~D  [C_0805]  73.53 38.45 180 top
PC302  10U_0805_25V6K~D  [C_0805]  73.53 38.45 180 bottom
PC303  0.1U_0402_25V6  [C_0402]  73.08 40.66 180 top
PC304  2200P_0402_50V7K  [C_0402]  73.08 39.77 180 top
PC305  1U_0402_25V6K  [C_0402]  77.43 34.38 180 top
PC306  1000P_0402_50V7K  [C_0402]  77.43 35.27 180 top
PC307  10U_0805_25V6K~D  [C_0805]  74.04 43.78 180 bottom
PC308  10U_0805_25V6K~D  [C_0805]  74.04 43.78 180 top
PC309  0.1U_0402_25V6  [C_0402]  81.94 46.89 90 top
PC310  0.1U_0402_25V6  [C_0402]  81.24 38.19 90 top
PC311  220U_6.3V_M  [C_APXK6R3ARA221MF451]  65.32 53.3 180 bottom
PC312  220U_6.3V_M  [C_APXK6R3ARA221MF451]  71.29 30.64 180 bottom
PC313  680P_0402_50V7K  [C_0402]  63.6 44.54 270 top
PC314  680P_0402_50V7K  [C_0402]  62.7 41.11 0 top
PC315  4.7U_0603_6.3V6K  [C_0603]  77.82 42.58 270 top
PC316  0.1U_0402_25V6  [C_0402]  85.76 49.63 270 top
PC700  1000P_0402_50V7K  [C_0402]  51.97 49.48 0 bottom
PC701  1000P_0402_50V7K  [C_0402]  52.79 55.27 0 top
PC702  0.1U_0402_25V6  [C_0402]  56.08 23.56 90 top
PC703  0.01U_0603_25V7K  [C_0603]  52.11 36.73 90 top
PC704  0.1U_0402_25V6  [C_0402]  42.2 40.66 0 top
PC705  2200P_0402_50V7K  [C_0402]  42.27 41.01 0 bottom
PC706  10U_0805_25V6K~D  [C_0805]  41.31 39.35 0 top
PC707  10U_0805_25V6K~D  [C_0805]  41.33 39.69 0 bottom
PC708  1U_0402_25V6K  [C_0402]  42.72 35.03 90 top
PC709  1000P_0402_50V7K  [C_0402]  41.78 35.03 90 top
PC710  0.1U_0603_25V7K  [C_0603]  34.76 39.17 90 bottom
PC711  0.1U_0402_25V6  [C_0402]  37.32 42.74 0 top
PC712  0.01UF_0402_25V7K  [C_0402]  36.27 40.56 270 bottom
PC713  0.047U_0402_25V7K  [C_0402]  39.02 39.65 0 top
PC714  2.2U_0603_16V6K  [C_0603]  38.9 37.19 0 top
PC715  1U_0603_25V6K  [C_0603]  40.01 40.77 180 top
PC716  22U_0805_25V6M  [C_0805]  51.74 37.6 270 bottom
PC717  22U_0805_25V6M  [C_0805]  50.03 37.6 270 bottom
PC718  22U_0805_25V6M  [C_0805]  48.31 37.6 270 bottom
PC719  680P_0402_50V7K  [C_0402]  43.87 35.82 90 top
PC720  0.1U_0402_25V6  [C_0402]  36.87 31.96 90 top
PC721  0.1U_0402_25V6  [C_0402]  35.99 32.86 180 top
PC722  0.1U_0402_25V6  [C_0402]  35.08 31.97 0 top
PC723  100P_0402_50V8J  [C_0402]  29.62 41.56 0 top
PC724  0.01UF_0402_25V7K  [C_0402]  34.02 43.53 180 top
PC725  100P_0402_50V8J  [C_0402]  29.62 40.6 0 top
PC800  0.1U_0402_16V7K  [C_0402]  234.99 54.96 180 top
PC801  0.1U_0402_25V6  [C_0402]  245.02 54.52 270 top
PC802  2200P_0402_50V7K  [C_0402]  246.04 54.52 270 top
PC803  22U_0805_25V6M  [C_0805]  250.74 60.39 90 top
PC804  22U_0805_25V6M  [C_0805]  252.52 60.39 90 top
PC805  22U_0805_25V6M  [C_0805]  248.96 60.39 90 top
PC806  1U_0402_25V6K  [C_0402]  242.23 62.95 180 top
PC807  1000P_0402_50V7K  [C_0402]  242.23 61.9 180 top
PC808  0.1U_0603_25V7K  [C_0603]  242.93 55.53 180 top
PC809  1U_0603_6.3V6M  [C_0603]  241.53 54.26 0 top
PC810  220U_D2 SX_2VY_R9M  [C_D2]  260.54 62 180 bottom
PC811  220U_D2 SX_2VY_R9M  [C_D2]  267.6 61.75 0 bottom
PC812  680P_0402_50V7K  [C_0402]  259.83 51.08 180 top
PC813  .047U_0402_16V7K  [C_0402]  239.84 50.43 90 top
PC814  820P_0402_50V7K  [C_0402]  235.46 51.35 270 top
PC4000  2200P_0402_50V7K  [C_0402]  121.69 104.67 180 bottom
PC4001  0.1U_0402_25V6  [C_0402]  121.69 103.76 180 bottom
PC4002  10U_0805_25V6K  [C_0805]  122.71 106.13 0 bottom
PC4003  1U_0402_25V6K  [C_0402]  121.67 105.61 180 bottom
PC4004  1000P_0402_50V7K  [C_0402]  121.7 106.52 180 bottom
PC4005  0.1U_0603_25V7K  [C_0603]  121.97 99.78 0 bottom
PC4006  22U_0603_6.3V6M  [C_0603]  128.7 93.01 180 bottom
PC4007  22U_0603_6.3V6M  [C_0603]  132.47 94.45 0 bottom
PC4008  22U_0603_6.3V6M  [C_0603]  128.7 94.26 180 bottom
PC4009  22U_0603_6.3V6M  [C_0603]  132.5 93.18 0 bottom
PC4010  330P_0402_50V7K  [C_0402]  128.95 101.94 180 bottom
PC4011  0.22U_0402_10V6K  [C_0402]  126.42 105.63 90 bottom
PC4012  2.2U_0402_16V6K  [C_0402]  125.18 99.85 0 bottom
PC4013  680P_0603_50V7K  [C_0603]  119.61 99.79 0 bottom
PC4014  1U_0603_6.3V6M  [C_0603]  127.48 99.98 0 bottom
PC5000  47P_0402_50V8J~D  [C_0402]  134.2 143.31 90 bottom
PC5001  0.1U_0402_25V6  [C_0402]  132.36 143.31 90 bottom
PC5002  1U_0402_16V6K  [C_0402]  137.22 141.84 270 bottom
PC5003  0.22U_0603_25V7K  [C_0603]  138.91 141.91 270 bottom
PC5004  330P_0402_50V7K  [C_0402]  131.88 141.75 0 bottom
PC5005  68P_0402_50V8J  [C_0402]  129.13 140.05 0 top
PC5006  1000P_0402_50V7K  [C_0402]  130.06 141.89 0 top
PC5007  6800P_0402_25V7K  [C_0402]  129.16 140.96 0 top
PC5008  1000P_0402_50V7K  [C_0402]  129.13 139.09 270 bottom
PC5009  470P_0402_50V7K  [C_0402]  128.18 138.24 270 top
PC5010  2200P_0402_50V7K  [C_0402]  143.8 141.76 180 top
PC5011  0.01UF_0402_25V7K  [C_0402]  143.8 139.86 180 top
PC5012  0.022U_0402_25V7K  [C_0402]  143.8 138.9 180 top
PC5013  .1U_0402_16V7K  [C_0402]  144.86 139.61 0 top
PC5014  0.01UF_0402_25V7K  [C_0402]  135.01 139.41 0 bottom
PC5015  1500P_0402_50V7K  [C_0402]  144.74 137.96 270 top
PC5016  0.01UF_0402_25V7K  [C_0402]  140.81 139.41 180 bottom
PC5017  0.15U_0402_16V7K  [C_0402]  132.79 138.17 180 bottom
PC5018  0.068U_0402_16V7K  [C_0402]  132.84 139.07 180 bottom
PC5019  2200P_0402_50V7K  [C_0402]  131.9 139.13 0 top
PC5020  330P_0402_50V7K  [C_0402]  142.89 136.11 0 top
PC5021  68P_0402_50V8J  [C_0402]  139.93 137.95 0 bottom
PC5022  2200P_0402_50V7K  [C_0402]  144.65 137.1 0 bottom
PC5023  680P_0402_50V7K  [C_0402]  144.67 138.08 0 bottom
PC5024  .1U_0402_16V7K  [C_0402]  131.03 138.2 180 bottom
PC5025  0.022U_0402_25V7K  [C_0402]  141.77 133.58 270 top
PC5026  0.022U_0402_25V7K  [C_0402]  131.92 137.25 0 top
PC5027  0.022U_0402_25V7K  [C_0402]  141.01 133.57 270 bottom
PC5028  0.022U_0402_25V7K  [C_0402]  140.86 133.58 270 top
PC5029  0.022U_0402_25V7K  [C_0402]  131.93 137.25 0 bottom
PC5030  .1U_0402_16V7K  [C_0402]  139.09 131.8 270 top
PC5031  2200P_0402_25V7K  [C_0402]  137.39 132.73 90 top
PC5032  0.22U_0402_16V7K  [C_0402]  138.3 132.71 90 bottom
PC5033  2200P_0402_50V7K  [C_0402]  139.04 133.58 270 top
PC5034  100P_0402_50V8J  [C_0402]  134.67 131.74 0 top
PC5035  0.01UF_0402_25V7K  [C_0402]  137.2 135.93 90 bottom
PC5036  330P_0402_50V7K  [C_0402]  131.92 135.35 0 top
PC5037  1000P_0402_50V7K  [C_0402]  135.56 130.93 0 bottom
PC5038  68P_0402_50V8J  [C_0402]  135.6 133.61 270 bottom
PC5039  680P_0402_50V7K  [C_0402]  134.63 131.8 270 bottom
PC5040  6800P_0402_25V7K  [C_0402]  135.57 131.83 0 bottom
PC5100  1U_0402_6.3V6K  [C_0402]  150.28 130.66 270 top
PC5101  1U_0402_6.3V6K  [C_0402]  147.98 127.98 0 top
PC5102  0.22U_0603_16V7K  [C_0603]  151.32 131.22 270 top
PC5103  100U_25V_M  [C_ECST250ADA101MF611]  149.52 133.6 270 bottom
PC5105  10U_0805_25V6K  [C_0805]  155.68 126.84 270 bottom
PC5106  10U_0805_25V6K  [C_0805]  148.82 126.48 270 top
PC5107  10U_0805_25V6K  [C_0805]  155.68 126.8 270 top
PC5108  0.1U_0402_25V6  [C_0402]  153.08 129.6 90 bottom
PC5109  2200P_0402_50V7K  [C_0402]  154.02 129.6 90 bottom
PC5110  1U_0402_25V6K  [C_0402]  118.48 115.22 180 bottom
PC5111  1000P_0402_50V7K  [C_0402]  118.48 114.26 180 bottom
PC5112  33P_0603_50V8J  [C_0603]  154.73 122.96 270 top
PC5113  1U_0402_6.3V6K  [C_0402]  136.07 126.84 270 top
PC5114  1U_0402_6.3V6K  [C_0402]  142.91 129.56 90 bottom
PC5115  0.22U_0603_16V7K  [C_0603]  142.72 131.22 270 top
PC5116  10U_0805_25V6K  [C_0805]  147.04 126.48 270 top
PC5117  10U_0805_25V6K  [C_0805]  144.76 130.08 90 bottom
PC5118  10U_0805_25V6K  [C_0805]  147.11 126.52 270 bottom
PC5119  0.1U_0402_25V6  [C_0402]  146.09 129.49 90 bottom
PC5120  2200P_0402_50V7K  [C_0402]  147.04 129.49 90 bottom
PC5121  1U_0402_25V6K  [C_0402]  146.62 127.57 0 bottom
PC5122  1000P_0402_50V7K  [C_0402]  146.62 128.49 0 bottom
PC5123  33P_0603_50V8J  [C_0603]  145.52 123.35 270 top
PC5124  1U_0402_6.3V6K  [C_0402]  157.58 126.85 270 top
PC5125  1U_0402_6.3V6K  [C_0402]  158.66 130.6 270 top
PC5126  0.22U_0603_16V7K  [C_0603]  160 131.22 270 top
PC5127  10U_0805_25V6K  [C_0805]  164.89 126.23 270 top
PC5128  10U_0805_25V6K  [C_0805]  163.11 126.23 270 top
PC5129  10U_0805_25V6K  [C_0805]  164.38 126.2 270 bottom
PC5130  0.1U_0402_25V6  [C_0402]  164 128.31 0 bottom
PC5131  2200P_0402_50V7K  [C_0402]  161.49 129.73 90 bottom
PC5132  1U_0402_25V6K  [C_0402]  162.43 129.72 90 bottom
PC5133  1000P_0402_50V7K  [C_0402]  164.05 127.34 0 bottom
PC5134  33P_0603_50V8J  [C_0603]  162.41 121.31 0 top
PC5200  1U_0402_6.3V6K  [C_0402]  115.34 118.77 0 top
PC5201  1U_0402_6.3V6K  [C_0402]  119.9 114.94 90 top
PC5202  0.22U_0603_16V7K  [C_0603]  114.83 120.12 0 bottom
PC5203  10U_0805_25V6K~D  [C_0805]  118.2 124.23 180 top
PC5204  10U_0805_25V6K~D  [C_0805]  119.37 124.23 0 top
PC5205  10U_0805_25V6K~D  [C_0805]  119.38 124.21 0 bottom
PC5206  0.1U_0402_25V6  [C_0402]  117.45 123.8 90 bottom
PC5207  1U_0402_25V6K  [C_0402]  116.37 122.5 180 bottom
PC5208  1000P_0402_50V7K  [C_0402]  118.37 123.76 90 bottom
PC5209  680P_0603_50V7K  [C_0603]  125.9 118.77 270 bottom
PC5210  2200P_0402_50V7K  [C_0402]  116.36 123.47 180 bottom
PC5211  1U_0402_6.3V6K  [C_0402]  116.43 125.89 180 top
PC5212  1U_0402_6.3V6K  [C_0402]  117.91 128.35 270 top
PC5213  0.22U_0603_16V7K  [C_0603]  114.91 128.12 0 bottom
PC5214  1U_0402_25V6K  [C_0402]  116.07 131.42 180 bottom
PC5215  1000P_0402_50V7K  [C_0402]  119.74 131.27 0 top
PC5216  10U_0805_25V6K  [C_0805]  118.1 131.85 180 top
PC5217  10U_0805_25V6K~D  [C_0805]  121.65 132.93 0 bottom
PC5218  10U_0805_25V6K  [C_0805]  121.65 132.93 0 top
PC5219  0.1U_0402_25V6  [C_0402]  116.07 130.53 180 bottom
PC5220  2200P_0402_50V7K  [C_0402]  119.74 132.22 0 top
PC5221  680P_0603_50V7K  [C_0603]  124.18 130.14 180 top
PC5222  0.22U_0603_16V7K  [C_0603]  168.12 130.01 270 bottom
PC5223  0.1U_0402_25V6  [C_0402]  171.56 126.7 90 bottom
PC5224  2200P_0402_50V7K  [C_0402]  172.45 126.7 90 bottom
PC5225  10U_0805_25V6K  [C_0805]  172.61 125.38 0 bottom
PC5226  10U_0805_25V6K  [C_0805]  170.96 122.14 0 top
PC5228  1U_0402_25V6K  [C_0402]  170.42 126.08 180 top
PC5229  1000P_0402_50V7K  [C_0402]  170.42 125.19 180 top
PC5230  1U_0402_6.3V6K  [C_0402]  166.14 128.62 0 bottom
PC5231  1U_0402_6.3V6K  [C_0402]  168.52 126.37 180 top
PC5232  680P_0603_50V7K  [C_0603]  168.5 120.68 270 top
PC5500  330U_D3_2VM_R6M  [C_D3]  163.37 95.04 0 top
PC5501  220U_D7_2VM_R6M  [C_EEFSS0D221R]  142.43 109.95 180 bottom
PC5502  220U_D7_2VM_R6M  [C_EEFSS0D221R]  152.15 109.88 180 bottom
PC5503  22U_0603_6.3V6M  [C_0603]  161.65 103.79 180 top
PC5504  22U_0603_6.3V6M  [C_0603]  166.6 88.77 0 top
PC5505  22U_0603_6.3V6M  [C_0603]  161.96 101.88 225 top
PC5506  22U_0603_6.3V6M  [C_0603]  163.55 108.74 0 bottom
PC5507  22U_0603_6.3V6M  [C_0603]  163.55 111.28 0 bottom
PC5508  22U_0603_6.3V6M  [C_0603]  163.55 110.01 0 bottom
PC5509  22U_0603_6.3V6M  [C_0603]  166.79 99.02 180 top
PC5510  22U_0603_6.3V6M  [C_0603]  163.55 107.47 0 bottom
PC5511  22U_0603_6.3V6M  [C_0603]  171.56 91.31 180 top
PC5512  22U_0603_6.3V6M  [C_0603]  160.57 93.02 270 top
PC5513  22U_0603_6.3V6M  [C_0603]  166.67 89.98 90 top
PC5514  22U_0603_6.3V6M  [C_0603]  169.14 91.31 180 top
PC5515  22U_0603_6.3V6M  [C_0603]  171.51 89.96 180 top
PC5516  22U_0603_6.3V6M  [C_0603]  160.57 94.8 90 top
PC5517  22U_0603_6.3V6M  [C_0603]  161.65 105.06 180 top
PC5518  1U_0402_6.3V6K  [C_0402]  165.5 87.61 180 top
PC5519  1U_0402_6.3V6K  [C_0402]  162.94 98.88 0 top
PC5520  1U_0402_6.3V6K  [C_0402]  170.36 98.22 0 top
PC5521  1U_0402_6.3V6K  [C_0402]  165.47 91.82 180 top
PC5522  1U_0402_6.3V6K  [C_0402]  165.35 90.69 180 top
PC5523  1U_0402_6.3V6K  [C_0402]  162.53 89.39 0 top
PC5524  .1U_0402_16V7K  [C_0402]  170.36 99.1 0 top
PC5525  .1U_0402_16V7K  [C_0402]  162.53 90.69 0 top
PC5526  .1U_0402_16V7K  [C_0402]  162.4 91.82 0 top
PC5527  .1U_0402_16V7K  [C_0402]  165.35 89.39 180 top
PC5528  .1U_0402_16V7K  [C_0402]  168.64 99.15 180 top
PC5529  .1U_0402_16V7K  [C_0402]  162.74 87.61 0 top
PC5530  .1U_0402_16V7K  [C_0402]  168.9 89.81 180 top
PC5531  .1U_0402_16V7K  [C_0402]  162.02 97.96 180 top
PC5532  .1U_0402_16V7K  [C_0402]  168.92 88.9 0 top
PC5533  .1U_0402_16V7K  [C_0402]  168.78 87.67 0 top
PC5534  .1U_0402_16V7K  [C_0402]  167.62 87.73 180 top
PC5535  .1U_0402_16V7K  [C_0402]  162.01 98.88 180 top
PC5536  .1U_0402_16V7K  [C_0402]  162.94 97.99 0 top
PC5537  .1U_0402_16V7K  [C_0402]  172.18 86.9 180 top
PC5538  .1U_0402_16V7K  [C_0402]  171.57 88.9 180 top
PC5539  470U_D2_2VM_R4.5M  [C_D2]  135.92 122.49 90 bottom
PC5540  330U_D3_2VM_R6M  [C_D3]  131.7 124.72 90 top
PC5541  47U_0805_6.3V6M  [C_0805]  154.4 90.4 180 top
PC5542  47U_0805_6.3V6M  [C_0805]  148.47 90.43 180 top
PC5543  47U_0805_6.3V6M  [C_0805]  148.5 94.46 180 top
PC5544  47U_0805_6.3V6M  [C_0805]  148.45 92.63 180 top
PC5545  47U_0805_6.3V6M  [C_0805]  149.66 90.4 0 top
PC5546  47U_0805_6.3V6M  [C_0805]  144.51 94.91 180 top
PC5547  47U_0805_6.3V6M  [C_0805]  149.79 92.56 0 top
PC5548  47U_0805_6.3V6M  [C_0805]  141.83 103.24 270 top
PC5549  47U_0805_6.3V6M  [C_0805]  149.85 94.47 0 top
PC5550  47U_0603_6.3V6M  [C_0603]  167.36 111.28 180 bottom
PC5551  47U_0603_6.3V6M  [C_0603]  167.36 110.01 180 bottom
PC5552  47U_0603_6.3V6M  [C_0603]  167.36 108.74 180 bottom
PC5553  22U_0603_6.3V6M  [C_0603]  137.01 103.98 270 top
PC5554  22U_0603_6.3V6M  [C_0603]  140.25 103.03 270 top
PC5555  22U_0603_6.3V6M  [C_0603]  143.49 103.31 270 top
PC5556  22U_0603_6.3V6M  [C_0603]  138.22 103.98 270 top
PC5557  22U_0603_6.3V6M  [C_0603]  152.95 105.76 0 top
PC5558  22U_0603_6.3V6M  [C_0603]  151.7 96.06 0 top
PC5559  22U_0603_6.3V6M  [C_0603]  149.16 96.06 0 top
PC5560  22U_0603_6.3V6M  [C_0603]  155.65 96.06 180 top
PC5561  22U_0603_6.3V6M  [C_0603]  154.13 93.39 180 top
PC5562  22U_0603_6.3V6M  [C_0603]  159.24 91.98 180 top
PC5563  22U_0603_6.3V6M  [C_0603]  155.32 91.99 0 top
PC5564  22U_0603_6.3V6M  [C_0603]  153.92 88.82 0 top
PC5565  22U_0603_6.3V6M  [C_0603]  146.68 88.82 0 top
PC5566  22U_0603_6.3V6M  [C_0603]  173.62 111.53 0 bottom
PC5567  22U_0603_6.3V6M  [C_0603]  171.24 110.33 0 bottom
PC5568  22U_0603_6.3V6M  [C_0603]  171.25 111.53 0 bottom
PC5569  22U_0603_6.3V6M  [C_0603]  170.27 110.33 180 bottom
PC5570  22U_0603_6.3V6M  [C_0603]  156.78 95.99 0 top
PC5571  22U_0603_6.3V6M  [C_0603]  154.11 94.71 180 top
PC5572  22U_0603_6.3V6M  [C_0603]  159.24 93.33 180 top
PC5573  22U_0603_6.3V6M  [C_0603]  155.48 90.66 0 top
PC5574  22U_0603_6.3V6M  [C_0603]  156.35 88.8 0 top
PC5575  22U_0603_6.3V6M  [C_0603]  149.09 88.82 0 top
PC5576  22U_0603_6.3V6M  [C_0603]  148.14 96.08 180 top
PC5577  22U_0603_6.3V6M  [C_0603]  159.24 94.66 180 top
PC5578  22U_0603_6.3V6M  [C_0603]  155.32 94.72 0 top
PC5579  22U_0603_6.3V6M  [C_0603]  155.38 93.33 0 top
PC5580  22U_0603_6.3V6M  [C_0603]  154.09 92 180 top
PC5581  22U_0603_6.3V6M  [C_0603]  173.75 97.96 180 top
PC5582  22U_0603_6.3V6M  [C_0603]  173.75 96.69 180 top
PC5583  22U_0603_6.3V6M  [C_0603]  173.93 93.53 180 top
PC5584  22U_0603_6.3V6M  [C_0603]  159.24 90.66 180 top
PC5585  22U_0603_6.3V6M  [C_0603]  170.27 111.53 180 bottom
PC5586  22U_0603_6.3V6M  [C_0603]  173.64 110.33 0 bottom
PC5587  22U_0603_6.3V6M  [C_0603]  151.51 88.82 0 top
